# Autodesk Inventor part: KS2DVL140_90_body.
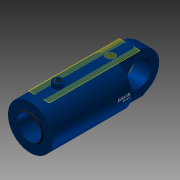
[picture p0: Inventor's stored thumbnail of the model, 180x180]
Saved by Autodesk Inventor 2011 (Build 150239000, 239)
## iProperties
Created: 2010-11
Document SubType Name: Modeling
Designer: TB
Mass: 405.061 g
Surface Area: 916.939 cm^2
Volume: 405.061 cm^3
Density: 1 g/cm^3
Author: TB
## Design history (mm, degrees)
sketch "Sketch2"
  geometry: L1 (-35, -3)-(-35, 3); L2 (-35, -9)-(-35, 9); L3 (-35, 0)-(-35, 82.5); L4 (-35, 82.5)-(-313, 82.5); L5 (-313, 82.5)-(-313, 82.5); L6 (-313, 82.5)-(-328, 82.5); L7 (-328, 82.5)-(-328, 49); L8 (-328, 49)-(-331, 46); L9 (-331, 46)-(-331, 45); L10 (-331, 45)-(-218, 45); L11 (-218, 45)-(-218, 70); L12 (-218, 70)-(-66, 70); L13 (-66, 70)-(-66, 0); L14 (-66, 0)-(-35, 0); L15 (-66, 0)-(-148.421, 0); L16 (-35, 9)-(-32, 12) reference; L17 (-32, 12)-(-35, 12) reference; L18 (-35, 12)-(-35, 9) reference; L19 (-32, 12)-(-35, 9) reference; L20 (-32, 12)-(-35, 12) reference; L21 (-35, 9)-(-35, 12) reference; L22 (-35, 9)-(-32, 12) reference; 1 further point
  constraints: 44 end point, 8 perpendicular, 6 parallel, 5 collinear, 2 horizontal, 2 vertical, 1 coincident, 1 midpoint, 1 point on line, 10 other
  dimensions: "DiaY" = 165 diameter of L4 L15; "DiaI" = 140 diameter of L12 L15; "d4" = 1 distance of L8.end L9.end; "d5" = 45 deg angle of L10 L8; "d6" = 3 distance between parallel lines of L7 L9; "DiaStang" = 90 diameter of L10 L15; "RindDia" = 165 diameter of L6 L15; "RingLengde" = 15 distance of L5.end L6.end; "RingTykk" = 110 distance between parallel lines of L11 L7; "KroppLengde" = 293 distance between parallel lines of L7 L3 (derived); "BunnTykkelse" = 31 distance between parallel lines of L13 L3
revolve "Kropp" sketch "Sketch2" stored, may be unused: angle "d13" = 90 deg
sketch "Sketch3"
  geometry: L1 (-66, -70)-(-66, 70) reference; L2 (-66, 0.01)-(-166, 0.01); L3 (-166, -0.01)-(-66, -0.01); A1 r 0.01 centre (-166, 0) between (-166, 0.01) and (-166, -0.01); A2 r 0.01 centre (-66, 0) between (-66, -0.01) and (-66, 0.01); 2 further points
  constraints: 4 end point, 4 point on circle, 4 tangent, 2 centre point, 1 coincident, 1 midpoint, 1 parallel, 1 perpendicular
  dimensions: "d17" = 0.01 radius of A2; "d18" = 100 distance of L2.start L2.end (= Slaglengde)
feature "BaneTransitionalConstraint" sketch "Sketch3" dims "d19" = 2, "d20" = 0
sketch "Sketch6"
  geometry: L1 (-115.5, 0)-(115.5, 0) reference; L2 (15.66, 81)-(-11.843, 81); L3 (82.5, 0)-(82.5, 31.248); L4 (-82.5, 0)-(-82.5, -18.451); A1 r 82.5 centre (0, 0) between (-82.5, 0) and (82.5, 0) reference; 2 further points
  constraints: 6 end point, 2 point on circle, 2 vertical, 2 other
  dimensions: "d30" = 81 distance from line of point (0, 0) L2 (computed from DiaY); "d31" = 0 deg angle of L1 L2 (computed from Vinkel_Plussport); "d37" = 90 deg angle of L2 L3; "d38" = 90 deg angle of L2 L4
  node "Projected Loop3"
workplane "Work Plane5"
sketch "Sketch7"
  geometry: L1 (15.66, -397.2)-(15.66, 66.2) reference; L2 (-19.633, -35)-(38.367, -35) reference; C1 r 17.5 at (15.66, -52.5); 1 further point
  constraints: 1 centre point, 1 point on line
  dimensions: "PortDia" = 35 diameter of C1
extrude "Extrusion2" cut sketch "Sketch7" stored distance "d34" = 1.5; taper "d35" = 0 deg
workplane "Work Plane7"
sketch "Sketch4"
  geometry: L1 (-16.68, -40)-(-16.68, -78.777); L2 (-16.68, -78.777)-(16.68, -78.777); L3 (16.68, -78.777)-(16.68, -40); L4 (16.68, -40)-(-16.68, -40); L5 (-40.643, -40)-(0, -40); L6 (-29, -35)-(29, -35); L7 (0, -35)-(0, -40); 2 further points
  constraints: 6 end point, 2 midpoint, 2 other
  dimensions: "d40" = 5 distance of L7.start L5.end
emboss "Emboss1" sketch "Sketch4" dims "d4" = 1, "d5" = 45 deg, "d6" = 3, "d22" = 0.2, "d23" = 0, "DiaI" = 140, "DiaY" = 165, "RindDia" = 165, "DiaStang" = 90, "RingTykk" = 110, "RingLengde" = 15, "KroppLengde" = 293 (derived), "BunnTykkelse" = 31
workplane "Work Plane8"
sketch "Sketch8"
  geometry: L1 (-29, -35)-(29, -35); L2 (0, -35)-(0, -40); L3 (-5.906, -110.587)-(-5.906, -40); L4 (-5.906, -40)-(5.906, -40); L5 (5.906, -40)-(5.906, -110.587); L6 (5.906, -110.587)-(-5.906, -110.587); L7 (82.5, -35)-(-82.5, -35); L8 (82.5, -35)-(-82.5, -35) reference; 3 further points
  constraints: 6 end point, 4 midpoint, 2 other
  dimensions: "d42" = 5 distance of L2.start L2.end
emboss "Emboss2" sketch "Sketch8" dims "d4" = 1, "d5" = 45 deg, "d6" = 3, "d43" = 0.2, "d44" = 0, "DiaI" = 140, "DiaY" = 165, "RindDia" = 165, "DiaStang" = 90, "RingTykk" = 110, "RingLengde" = 15, "KroppLengde" = 293 (derived), "BunnTykkelse" = 31
sketch "Sketch9"
  geometry: A1 r 12.5 centre (9.367, -52.5) between (0, -60.776) and (18.735, -60.776) reference; 1 further point
hole "Hole1" sketch "Sketch9" at (9.367, -52.5) diameter "d45" = 14.95; stored, may be unused: countersink angle "d49" = 82 deg, drill point angle "d51" = 118 deg; dims "d46" = 6, "d47" = 3.023, "d48" = 2, "DiaInvPluss" = 24.5
workplane "Work Plane9"
sketch "Sketch10"
  geometry: L1 (-115.5, 0)-(115.5, 0) reference; L2 (0, 82.5)-(13.136, 82.5); L3 (0, 82.5)-(0, 31.79); L4 (17.5, 80.623)-(17.5, 100); L5 (17.5, 100)-(0, 100); L6 (0, 100)-(0, 82.5); L7 (0, 82.5)-(17.5, 80.623); C1 r 82.5 at (0, 0) reference; A1 r 82.5 centre (0, 0) between (0, 82.5) and (17.5, 80.623); 1 further point
  constraints: 12 end point, 4 perpendicular, 2 concentric, 2 point on circle, 1 centre point, 1 point on line, 1 tangent
  dimensions: "d53" = 0 deg angle of L1 L2 (computed from Vinkel_Minusport); "DiaUtvStussMinus" = 35 diameter of L4 L3; "HøydeStussMinuss" = 17.5 distance between parallel lines of L2 L5
revolve "Revolution2" sketch "Sketch10" stored, may be unused: angle "d56" = 90 deg
hole "Hole2" diameter "d59" = 24.117; stored, may be unused: countersink angle "d63" = 82 deg, drill point angle "d65" = 118 deg; dims "d57" = 10, "d58" = 10, "d60" = 6, "d61" = 3.023, "d62" = 2, "DiaInvStussMinus" = 24.5
fillet "Fillet1" dims "d66" = 2
sketch "Sketch15"
  geometry: L1 (30, -76.852)-(30, 76.852); L2 (-30, -76.852)-(-30, 76.852); L3 (0, 115.5)-(0, -115.5) reference; A1 r 82.5 centre (0, 0) between (30, -76.852) and (-30, -76.852) reference; A2 r 82.5 centre (0, 0) between (30, 76.852) and (-30, 76.852); A3 r 82.5 centre (0, 0) between (-30, -76.852) and (30, -76.852)
  constraints: 8 point on circle, 4 end point, 4 point on line, 2 centre point, 2 concentric, 2 parallel, 1 coincident
  dimensions: "EyeBunnTykk" = 30 distance from line of L1 A1.centre; "EyeBunnTykk2" = 30 distance from line of A1.centre L2
extrude "Extrusion6" join sketch "Sketch15" taper "d98" = 0 deg; distance "LengdeEyeMinussBunntykk" = 153
sketch "Sketch16"
  geometry: L1 (-327, 82.5)-(118, 82.5) reference; L2 (-327, -82.5)-(118, -82.5) reference; L3 (-327, 82.5)-(118, 82.5) reference; L4 (118, 82.5)-(118, 76.852) reference; L5 (118, -76.852)-(118, 76.852) reference; L6 (-419.086, 0)-(225.515, 0) reference; L7 (43.5, 82.5)-(118, 82.5); L8 (118, 82.5)-(118, 8); A1 r 74.5 centre (43.5, 8) between (118, 8) and (43.5, 82.5); 6 further points; 2 other entities
  constraints: 4 end point, 4 tangent, 2 point on circle, 2 point on line, 1 centre point, 1 collinear, 1 perpendicular, 2 other
  dimensions: "d137" = 8 distance from line of L8.end L6
extrude "Extrusion7" cut sketch "Sketch16" taper "d102" = 0 deg; stored distance "ExtruEyeBunn" = 50
mirror "Mirror1"
sketch "Sketch20"
  geometry: L1 (-327, 82.5)-(118, 82.5) reference; L2 (118, -76.852)-(118, 76.852) reference; L3 (118, 82.5)-(118, 76.852) reference; L4 (-417.146, 0)-(213.879, 0) reference; L5 (-35, -76.852)-(-35, 76.852) reference; L6 (-35, 0)-(45, 0); L7 (45, 0)-(45, 20.918); L8 (56.067, 78.481)-(82.5, 63.22); A1 r 35 centre (43.843, 47.5) between (43.843, 82.5) and (43.843, 82.5); A2 r 30 centre (41.067, 52.5) between (56.067, 78.481) and (41.067, 82.5); A3 r 73 centre (46, 0) between (118, 12.042) and (82.5, 63.22); 3 further points
  constraints: 7 point on line, 6 end point, 6 point on circle, 4 tangent, 3 centre point, 1 coincident, 1 midpoint, 1 perpendicular
  dimensions: "d147" = 80 distance of L6.start L6.end; "d163" = 1 distance of point (46, 0) L6.end; "d165" = 73 radius of A3; "d166" = 30 deg angle of L1 L8; "d167" = 30 radius of A2
extrude "Extrusion10" cut sketch "Sketch20" stored distance "d144" = 10; taper "d145" = 0 deg
mirror "Mirror2"
sketch "Sketch17"
  geometry: L1 (153.704, 0)-(0, 0) reference; L2 (76.852, -385.8)-(76.852, 242.8) reference; C1 r 45.5 at (76.852, 80); 1 further point
  constraints: 1 centre point, 1 point on line
  dimensions: "DiaHullEyeBunn" = 91 diameter of C1; "d125" = 80 distance from line of C1.centre L1
extrude "Extrusion8" cut sketch "Sketch17" taper "d105" = 0 deg; distance "ExtruHullEye" = 60
pattern_circular "Circular Pattern1 Only Subsea" dims "d108" = 180 deg (derived)
workplane "Work Plane11"
sketch "Sketch18"
  geometry: L1 (0, -79.2)-(0, 13.2) reference; L2 (70, -66)-(-70, -66) reference; L3 (70, -66)-(-70, -66) reference; C1 r 17.5 at (0, -31); 1 further point
  constraints: 1 centre point
  dimensions: "DiaForsenkPlussPort" = 35 diameter of C1; "PlassPlussport" = 35 distance from line of L2 C1.centre
extrude "Extrusion9" cut sketch "Sketch18" stored distance "d113" = 10; taper "d114" = 0 deg
sketch "Sketch19"
  geometry: 10 further points
  constraints: 1 other
hole "Hole3" sketch "Sketch19" at (0, -31) diameter "d115" = 24.117; stored, may be unused: countersink angle "d119" = 90 deg, drill point angle "d121" = 118 deg; dims "d116" = 6, "d117" = 4, "d118" = 2, "d120" = 14.5
pattern_circular "Circular Pattern2 Only Subsea" dims angle "d123" = 360 deg
body "Solid1"
chamfer "Chamfer" distance "Chamfer" = 1; stored, may be unused: second distance "d15" = 2, angle "d16" = 45 deg
node "Projected Loop2"
body "Srf1"
node "Projected Loop10"
other parameters: "Slaglengde" = 100, "Forlengelse_rør" = 0, "Vinkel_Plussport" = 0 [user parameter; used in 1 equation term], "Vinkel_Minusport" = 0, "d32" = 90 deg, "d39" = 90 deg, "d41" = 90 deg, "PortMinusPlass" = -102, "Minusport2" = 180 deg, "ForsenkningPlussPort" = 80.7 (derived), "EyeLengdeUBunn" = 136, "d164" = 73
